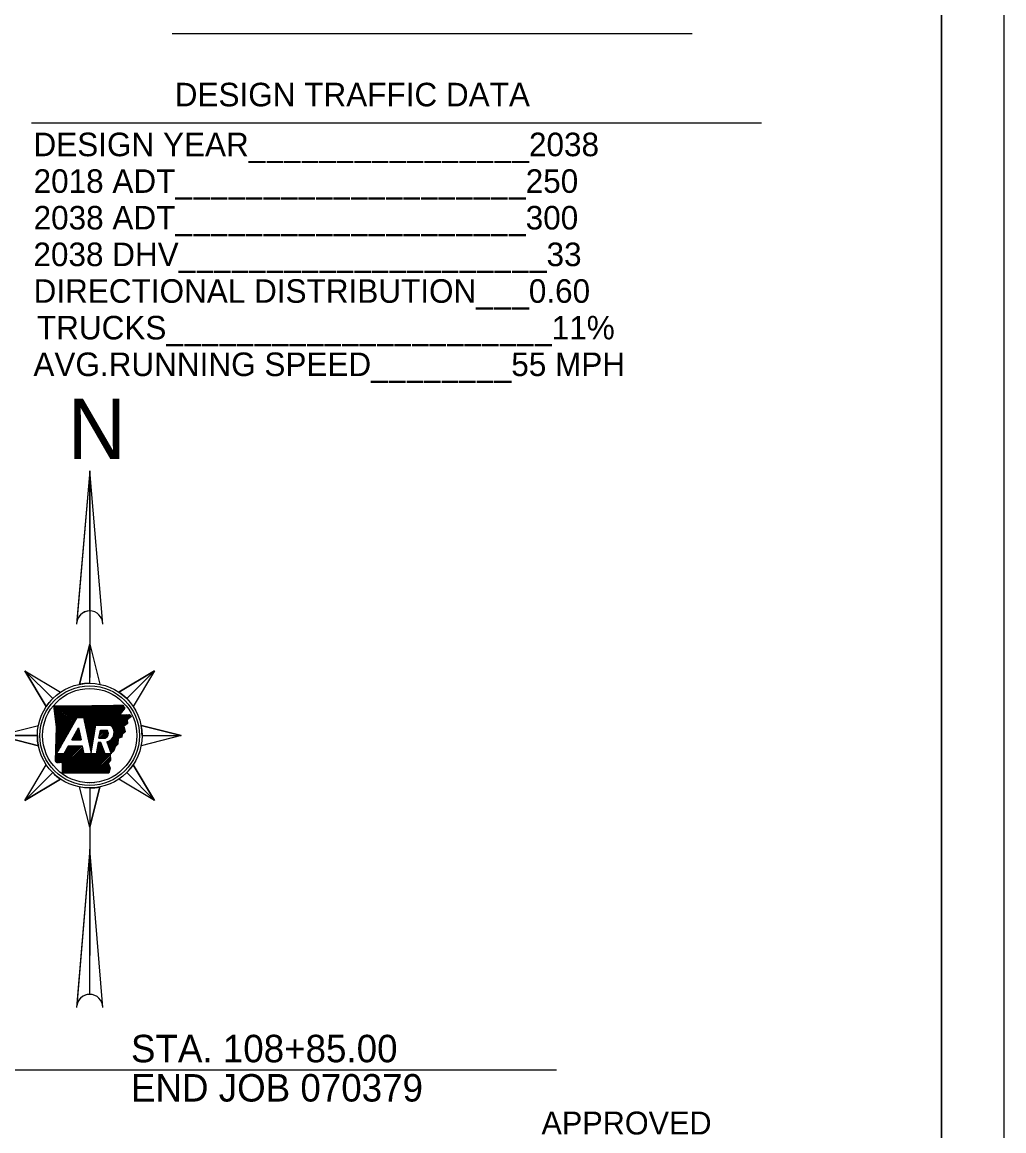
# Model space of a CAD drawing. Extents: x -492261 to -432772, y 1441225 to 1452922.
# Drawn here: x -457499 to -456748, y 1450946 to 1451793 of the extents above; entities that cross this region are included whole.
import ezdxf

# ---------------------------------------------------------------- set-up
doc = ezdxf.new("R2010")
doc.units = 0
for name, color, linetype in [('Default', 7, 'Continuous'), ('R_Border', 7, 'Continuous'), ('R_Border PE', 7, 'Continuous'), ('R_Draft', 7, 'Continuous'), ('R_No Plot', 7, 'Continuous'), ('R_Water Annot', 7, 'Continuous')]:
    doc.layers.add(name, color=color, linetype=linetype)

msp = doc.modelspace()

# ---------------------------------------------------------------- linework, layer by layer
at = {"layer": 'Default'}
for p, q in [((-457383.88, 1451784.26), (-456986.47, 1451784.26)), ((-457491.53, 1451716.09), (-456933.55, 1451716.09))]:
    msp.add_line(p, q, dxfattribs=at)
at = {"layer": 'R_Border'}
msp.add_line((-456795.84, 1450553.05), (-456795.84, 1452607.65), dxfattribs=at)
at = {"layer": 'R_Draft'}
for p, q in [((-457446.98, 1451449.98), (-457456.83, 1451334.68)), ((-457446.98, 1451449.98), (-457446.98, 1451292.07)), ((-457446.98, 1451342.98), (-457446.98, 1451449.98)), ((-457456.69, 1451336.29), (-457456.24, 1451336.73)), ((-457456.64, 1451336.9), (-457455.73, 1451337.82)), ((-457446.98, 1451317.7), (-457454.77, 1451286.93)), ((-457446.98, 1451287.7), (-457446.98, 1451317.7)), ((-457496.47, 1451297.2), (-457475.26, 1451275.98)), ((-457475.26, 1451275.98), (-457496.47, 1451297.2)), ((-457496.47, 1451297.2), (-457480.23, 1451269.93)), ((-457397.48, 1451297.2), (-457424.74, 1451280.95)), ((-457418.69, 1451275.98), (-457397.48, 1451297.2)), ((-457418.69, 1451275.98), (-457397.48, 1451297.2)), ((-457472.24, 1451233.69), (-457456.46, 1451261.56)), ((-457456.46, 1451261.56), (-457451.77, 1451261.56)), ((-457460.63, 1451244.63), (-457455.47, 1451253.74)), ((-457442.25, 1451255.75), (-457431.29, 1451255.75)), ((-457438.83, 1451251.81), (-457433.69, 1451251.81)), ((-457376.98, 1451247.7), (-457407.74, 1451255.49)), ((-457516.98, 1451247.7), (-457486.98, 1451247.7)), ((-457486.98, 1451247.7), (-457516.98, 1451247.7)), ((-457516.98, 1451247.7), (-457486.21, 1451239.91)), ((-457463.51, 1451239.54), (-457466.82, 1451233.69)), ((-457452.43, 1451239.54), (-457463.51, 1451239.54)), ((-457460.63, 1451244.63), (-457453.52, 1451244.63)), ((-457438.55, 1451242.55), (-457440.45, 1451242.55)), ((-457439.87, 1451245.86), (-457435.17, 1451245.86)), ((-457435.27, 1451233.69), (-457438.55, 1451242.55)), ((-457433.91, 1451243.02), (-457430.46, 1451233.69)), ((-457406.98, 1451247.7), (-457376.98, 1451247.7)), ((-457406.98, 1451247.7), (-457376.98, 1451247.7)), ((-457466.82, 1451233.69), (-457472.24, 1451233.69)), ((-457441.99, 1451233.69), (-457451.18, 1451233.69)), ((-457430.46, 1451233.69), (-457435.27, 1451233.69)), ((-457397.48, 1451198.2), (-457413.73, 1451225.46)), ((-457496.47, 1451198.2), (-457475.26, 1451219.42)), ((-457475.26, 1451219.42), (-457496.47, 1451198.2)), ((-457496.47, 1451198.2), (-457469.21, 1451214.45)), ((-457418.69, 1451219.42), (-457397.48, 1451198.2)), ((-457418.69, 1451219.42), (-457397.48, 1451198.2)), ((-457446.98, 1451177.7), (-457439.19, 1451208.47)), ((-457446.98, 1451207.7), (-457446.98, 1451207.7)), ((-457446.98, 1451207.7), (-457446.98, 1451079.65)), ((-457446.98, 1451207.7), (-457446.98, 1451177.7)), ((-457446.98, 1451160.98), (-457456.84, 1451041.62)), ((-457446.98, 1451049.98), (-457446.98, 1451160.98)), ((-457691.3, 1450992.37), (-457090.15, 1450992.37))]:
    msp.add_line(p, q, dxfattribs=at)
for points in [[(-457436.98, 1451332.98), (-457446.98, 1451449.98), (-457456.98, 1451332.98)], [(-457454.77, 1451286.93), (-457446.98, 1451317.7), (-457439.19, 1451286.93)], [(-457480.23, 1451269.93), (-457496.47, 1451297.2), (-457469.21, 1451280.95)], [(-457424.74, 1451280.95), (-457397.48, 1451297.2), (-457413.73, 1451269.93)], [(-457474.29, 1451270.6), (-457458.68, 1451270.59), (-457444.98, 1451270.62), (-457428.82, 1451270.87), (-457421.33, 1451271.04)], [(-457473.16, 1451228.37), (-457472.29, 1451254.55), (-457474.29, 1451270.6)], [(-457451.77, 1451261.56), (-457445.96, 1451234.43), (-457442.25, 1451255.75)], [(-457416.43, 1451263.87), (-457415.08, 1451262.46), (-457418.44, 1451259.69), (-457418.08, 1451256.9), (-457420.97, 1451254.99), (-457419.98, 1451250.7), (-457422.21, 1451248.66), (-457422.41, 1451246.46), (-457425.11, 1451245.48), (-457425.53, 1451241.32), (-457427.48, 1451239.23), (-457428.42, 1451236.1), (-457431.25, 1451233.5), (-457431.04, 1451228.93), (-457432.96, 1451226.77), (-457431.21, 1451222.84), (-457432.42, 1451218.95)], [(-457423.65, 1451263.5), (-457416.32, 1451263.88)], [(-457486.21, 1451239.91), (-457516.98, 1451247.7), (-457486.21, 1451255.49)], [(-457455.47, 1451253.74), (-457453.52, 1451244.63)], [(-457439.87, 1451245.86), (-457438.83, 1451251.81)], [(-457407.74, 1451255.49), (-457376.98, 1451247.7), (-457407.74, 1451239.91)], [(-457451.18, 1451233.69), (-457452.43, 1451239.54)], [(-457440.45, 1451242.55), (-457441.99, 1451233.69)], [(-457469.21, 1451214.45), (-457496.47, 1451198.2), (-457480.23, 1451225.46)], [(-457432.42, 1451218.95), (-457467.8, 1451219), (-457467.82, 1451226.81)], [(-457413.73, 1451225.46), (-457397.48, 1451198.2), (-457424.74, 1451214.45)], [(-457439.19, 1451208.47), (-457446.98, 1451177.7), (-457454.77, 1451208.47)], [(-457436.98, 1451039.98), (-457446.98, 1451160.98), (-457456.98, 1451039.98)]]:
    msp.add_lwpolyline(points, dxfattribs=at)
for radius in [40, 36]:
    msp.add_circle((-457446.98, 1451247.7), radius, dxfattribs=at)
for centre, radius, start, end in [((-457446.98, 1451332.98), 10, 0, 180), ((-457446.98, 1451332.98), 10, 90, 170.22959), ((-457446.98, 1451247.7), 40, 90, 101.22909), ((-457446.98, 1451247.7), 40, 135, 146.22909), ((-457446.98, 1451247.7), 40, 45, 56.22909), ((-457436.29, 1451249.3), 3.62, 288.12683, 43.89016), ((-457435.36, 1451249.95), 7.08, 281.86262, 54.87052), ((-457446.98, 1451247.7), 40, 0, 11.22909), ((-457446.98, 1451247.7), 40, 180, 191.22909), ((-457446.98, 1451247.7), 40, 315, 326.22909), ((-457446.98, 1451247.7), 40, 225, 236.22909), ((-457446.98, 1451247.7), 40, 270, 281.22909), ((-457446.98, 1451039.98), 10, 0, 180), ((-457446.98, 1451039.98), 10, 90, 170.5511)]:
    msp.add_arc(centre, radius, start, end, dxfattribs=at)
for points in [[(-457421.33, 1451271.04), (-457421.28, 1451270.62), (-457421.15, 1451270.39), (-457421.13, 1451269.99), (-457420.96, 1451269.82), (-457420.68, 1451269.64), (-457420.43, 1451269.36), (-457420.38, 1451269.03), (-457420.45, 1451268.7), (-457420.47, 1451268.32), (-457420.51, 1451267.99), (-457420.57, 1451267.69), (-457420.8, 1451267.45), (-457421.02, 1451267.28), (-457421.22, 1451267.07), (-457421.37, 1451266.86), (-457421.62, 1451266.63), (-457421.87, 1451266.39), (-457422.07, 1451266.18), (-457422.28, 1451265.91), (-457422.37, 1451265.61), (-457422.6, 1451265.39), (-457422.77, 1451265.2), (-457423, 1451264.94), (-457423.12, 1451264.68), (-457423.34, 1451264.38), (-457423.39, 1451264.09), (-457423.53, 1451263.86), (-457423.54, 1451263.82)], [(-457467.82, 1451226.81), (-457467.78, 1451226.79), (-457467.96, 1451226.92), (-457468.21, 1451227.04), (-457468.49, 1451227.06), (-457468.85, 1451227.11), (-457469.15, 1451227.14), (-457469.46, 1451227.34), (-457469.79, 1451227.13), (-457470.15, 1451226.98), (-457470.37, 1451227.15), (-457470.65, 1451227.03), (-457470.84, 1451227.09), (-457471.18, 1451226.86), (-457471.5, 1451226.95), (-457471.73, 1451226.88), (-457472.02, 1451226.89), (-457472.08, 1451227.22), (-457472.36, 1451227.27), (-457472.6, 1451227.4), (-457472.76, 1451227.74), (-457472.88, 1451228), (-457473.16, 1451228.37)]]:
    msp.add_spline(points, degree=3, dxfattribs=at)
at = {"layer": 'R_No Plot'}
for points in [[(-460081.71, 1452646.6), (-456748.31, 1452646.6), (-456748.31, 1450513.22), (-460081.71, 1450513.22)], [(-457618.44, 1452607.65), (-457618.44, 1452508.85), (-457261.12, 1452508.85), (-457261.12, 1452479.65), (-457029.12, 1452479.65), (-457029.12, 1452236.32), (-456795.84, 1452236.32), (-456795.84, 1450553.05), (-459957.64, 1450553.05), (-459957.64, 1452607.65)]]:
    msp.add_lwpolyline(points, close=True, dxfattribs=at)
at = {"layer": 'R_Water Annot'}
for p, q in [((-457474.24, 1451270.24), (-457473.89, 1451270.6)), ((-457474.12, 1451269.24), (-457472.76, 1451270.6)), ((-457473.99, 1451268.23), (-457471.63, 1451270.6)), ((-457473.87, 1451267.23), (-457470.5, 1451270.6)), ((-457473.74, 1451266.22), (-457469.37, 1451270.59)), ((-457473.62, 1451265.21), (-457468.24, 1451270.59)), ((-457473.49, 1451264.21), (-457467.11, 1451270.59)), ((-457473.36, 1451263.2), (-457465.97, 1451270.59)), ((-457473.24, 1451262.2), (-457464.84, 1451270.59)), ((-457473.11, 1451261.19), (-457463.71, 1451270.59)), ((-457472.99, 1451260.18), (-457462.58, 1451270.59)), ((-457472.86, 1451259.18), (-457461.45, 1451270.59)), ((-457472.74, 1451258.17), (-457460.32, 1451270.59)), ((-457472.61, 1451257.17), (-457459.19, 1451270.59)), ((-457472.58, 1451245.89), (-457447.85, 1451270.61)), ((-457472.54, 1451247.06), (-457448.99, 1451270.61)), ((-457472.5, 1451248.23), (-457450.12, 1451270.61)), ((-457472.49, 1451256.16), (-457458.06, 1451270.59)), ((-457472.46, 1451249.4), (-457451.26, 1451270.6)), ((-457472.42, 1451250.57), (-457452.39, 1451270.6)), ((-457472.38, 1451251.74), (-457453.52, 1451270.6)), ((-457472.36, 1451255.15), (-457456.92, 1451270.59)), ((-457472.34, 1451252.91), (-457454.66, 1451270.6)), ((-457472.3, 1451254.08), (-457455.79, 1451270.59)), ((-457455.77, 1451261.56), (-457446.72, 1451270.61)), ((-457454.64, 1451261.56), (-457445.59, 1451270.62)), ((-457453.51, 1451261.56), (-457444.45, 1451270.63)), ((-457452.38, 1451261.56), (-457443.3, 1451270.64)), ((-457451.68, 1451261.13), (-457442.15, 1451270.66)), ((-457451.48, 1451260.2), (-457441, 1451270.68)), ((-457451.28, 1451259.27), (-457439.85, 1451270.7)), ((-457451.08, 1451258.34), (-457438.7, 1451270.71)), ((-457450.88, 1451257.4), (-457437.55, 1451270.73)), ((-457450.68, 1451256.47), (-457436.4, 1451270.75)), ((-457450.48, 1451255.54), (-457435.25, 1451270.77)), ((-457450.28, 1451254.61), (-457434.1, 1451270.79)), ((-457450.08, 1451253.68), (-457432.95, 1451270.8)), ((-457449.88, 1451252.75), (-457431.8, 1451270.82)), ((-457449.68, 1451251.81), (-457430.66, 1451270.84)), ((-457449.48, 1451250.88), (-457429.51, 1451270.86)), ((-457449.28, 1451249.95), (-457428.35, 1451270.88)), ((-457449.08, 1451249.02), (-457427.19, 1451270.91)), ((-457441.22, 1451255.75), (-457426.04, 1451270.93)), ((-457440.09, 1451255.75), (-457424.88, 1451270.96)), ((-457438.96, 1451255.75), (-457423.72, 1451270.99)), ((-457437.83, 1451255.75), (-457422.56, 1451271.01)), ((-457436.7, 1451255.75), (-457421.4, 1451271.04)), ((-457435.57, 1451255.75), (-457421.15, 1451270.16)), ((-457434.44, 1451255.75), (-457420.6, 1451269.58)), ((-457433.3, 1451255.75), (-457420.46, 1451268.59)), ((-457432.17, 1451255.75), (-457423.04, 1451264.88)), ((-457472.65, 1451243.55), (-457458.82, 1451257.38)), ((-457472.61, 1451244.72), (-457457.35, 1451259.99)), ((-457431.14, 1451255.64), (-457423.26, 1451263.52)), ((-457430.53, 1451255.13), (-457422.07, 1451263.58)), ((-457429.97, 1451254.55), (-457420.88, 1451263.65)), ((-457429.49, 1451253.91), (-457419.69, 1451263.71)), ((-457429.07, 1451253.19), (-457418.49, 1451263.77)), ((-457428.72, 1451252.41), (-457417.3, 1451263.83)), ((-457428.54, 1451248.07), (-457418.27, 1451258.34)), ((-457428.46, 1451251.54), (-457416.23, 1451263.77)), ((-457428.31, 1451250.56), (-457415.7, 1451263.17)), ((-457428.3, 1451249.44), (-457418.4, 1451259.34)), ((-457419.54, 1451255.94), (-457418.14, 1451257.34)), ((-457416.2, 1451261.54), (-457415.17, 1451262.57)), ((-457472.77, 1451240.04), (-457463.26, 1451249.55)), ((-457472.73, 1451241.21), (-457461.78, 1451252.16)), ((-457472.69, 1451242.38), (-457460.3, 1451254.77)), ((-457460.57, 1451244.63), (-457454.76, 1451250.44)), ((-457459.44, 1451244.63), (-457454.56, 1451249.51)), ((-457459.22, 1451247.11), (-457454.96, 1451251.37)), ((-457458.31, 1451244.63), (-457454.36, 1451248.58)), ((-457457.75, 1451249.72), (-457455.16, 1451252.31)), ((-457456.27, 1451252.33), (-457455.36, 1451253.24)), ((-457448.88, 1451248.09), (-457442.46, 1451254.51)), ((-457448.68, 1451247.15), (-457442.7, 1451253.14)), ((-457448.48, 1451246.22), (-457442.94, 1451251.77)), ((-457448.29, 1451245.29), (-457443.18, 1451250.39)), ((-457448.09, 1451244.36), (-457443.42, 1451249.02)), ((-457439.86, 1451245.86), (-457433.91, 1451251.81)), ((-457439.63, 1451247.22), (-457435.04, 1451251.81)), ((-457439.39, 1451248.59), (-457436.17, 1451251.81)), ((-457439.15, 1451249.96), (-457437.3, 1451251.81)), ((-457438.91, 1451251.33), (-457438.44, 1451251.81)), ((-457438.73, 1451245.86), (-457433.28, 1451251.31)), ((-457437.6, 1451245.86), (-457432.9, 1451250.56)), ((-457436.47, 1451245.86), (-457432.69, 1451249.64)), ((-457435.34, 1451245.86), (-457432.78, 1451248.41)), ((-457433.21, 1451241.13), (-457420.67, 1451253.68)), ((-457432.9, 1451240.31), (-457420.45, 1451252.76)), ((-457432.6, 1451239.48), (-457420.24, 1451251.84)), ((-457432.29, 1451238.66), (-457420.03, 1451250.92)), ((-457429.52, 1451245.95), (-457420.88, 1451254.6)), ((-457472.89, 1451236.53), (-457467.69, 1451241.73)), ((-457472.85, 1451237.7), (-457466.21, 1451244.34)), ((-457472.81, 1451238.87), (-457464.73, 1451246.94)), ((-457472.72, 1451227.64), (-457460.83, 1451239.54)), ((-457472.05, 1451227.19), (-457459.7, 1451239.54)), ((-457471.23, 1451226.87), (-457458.56, 1451239.54)), ((-457469.89, 1451227.08), (-457457.43, 1451239.54)), ((-457468.74, 1451227.1), (-457456.3, 1451239.54)), ((-457467.85, 1451226.85), (-457455.17, 1451239.54)), ((-457467.82, 1451225.76), (-457454.04, 1451239.54)), ((-457467.81, 1451224.63), (-457452.91, 1451239.54)), ((-457465.54, 1451235.95), (-457461.96, 1451239.54)), ((-457464.06, 1451238.56), (-457463.09, 1451239.54)), ((-457457.18, 1451244.63), (-457454.16, 1451247.65)), ((-457456.05, 1451244.63), (-457453.96, 1451246.71)), ((-457454.92, 1451244.63), (-457453.76, 1451245.78)), ((-457453.79, 1451244.63), (-457453.56, 1451244.85)), ((-457447.89, 1451243.43), (-457443.66, 1451247.65)), ((-457447.69, 1451242.49), (-457443.9, 1451246.28)), ((-457447.49, 1451241.56), (-457444.14, 1451244.91)), ((-457447.29, 1451240.63), (-457444.37, 1451243.54)), ((-457447.09, 1451239.7), (-457444.61, 1451242.17)), ((-457446.89, 1451238.77), (-457444.85, 1451240.8)), ((-457446.69, 1451237.83), (-457445.09, 1451239.43)), ((-457441.56, 1451236.18), (-457437.64, 1451240.1)), ((-457441.32, 1451237.55), (-457437.94, 1451240.92)), ((-457441.08, 1451238.92), (-457438.25, 1451241.75)), ((-457440.84, 1451240.29), (-457438.58, 1451242.55)), ((-457440.6, 1451241.66), (-457439.71, 1451242.55)), ((-457433.82, 1451242.79), (-457433.47, 1451243.13)), ((-457433.51, 1451241.96), (-457431.36, 1451244.11)), ((-457431.99, 1451237.83), (-457425.2, 1451244.62)), ((-457431.68, 1451237), (-457425.33, 1451243.36)), ((-457431.38, 1451236.18), (-457425.45, 1451242.1)), ((-457423.9, 1451245.92), (-457422.31, 1451247.51)), ((-457473.14, 1451228.35), (-457467.81, 1451233.69)), ((-457473.12, 1451229.51), (-457468.94, 1451233.69)), ((-457473.08, 1451230.68), (-457470.07, 1451233.69)), ((-457473.04, 1451231.85), (-457471.2, 1451233.69)), ((-457473, 1451233.02), (-457472.12, 1451233.9)), ((-457472.96, 1451234.19), (-457470.64, 1451236.51)), ((-457472.92, 1451235.36), (-457469.16, 1451239.12)), ((-457467.81, 1451223.5), (-457452.31, 1451239)), ((-457467.81, 1451222.37), (-457452.11, 1451238.07)), ((-457467.8, 1451221.24), (-457451.91, 1451237.14)), ((-457467.8, 1451220.12), (-457451.71, 1451236.2)), ((-457467.78, 1451219), (-457451.51, 1451235.27)), ((-457466.65, 1451219), (-457451.31, 1451234.34)), ((-457465.52, 1451219), (-457450.84, 1451233.69)), ((-457464.39, 1451219), (-457449.71, 1451233.69)), ((-457463.26, 1451219), (-457448.57, 1451233.69)), ((-457462.14, 1451218.99), (-457447.44, 1451233.69)), ((-457461.01, 1451218.99), (-457446.31, 1451233.69)), ((-457459.88, 1451218.99), (-457445.18, 1451233.69)), ((-457458.75, 1451218.99), (-457444.05, 1451233.69)), ((-457457.62, 1451218.99), (-457442.92, 1451233.69)), ((-457456.49, 1451218.99), (-457437.03, 1451238.44)), ((-457455.36, 1451218.98), (-457436.72, 1451237.62)), ((-457454.23, 1451218.98), (-457436.42, 1451236.79)), ((-457453.1, 1451218.98), (-457436.11, 1451235.97)), ((-457451.97, 1451218.98), (-457435.81, 1451235.14)), ((-457450.84, 1451218.98), (-457435.5, 1451234.31)), ((-457449.71, 1451218.97), (-457435, 1451233.69)), ((-457448.58, 1451218.97), (-457433.87, 1451233.69)), ((-457447.45, 1451218.97), (-457432.73, 1451233.69)), ((-457446.49, 1451236.9), (-457445.33, 1451238.06)), ((-457446.32, 1451218.97), (-457431.6, 1451233.69)), ((-457446.29, 1451235.97), (-457445.57, 1451236.69)), ((-457446.09, 1451235.04), (-457445.81, 1451235.32)), ((-457445.19, 1451218.97), (-457431.22, 1451232.93)), ((-457444.06, 1451218.96), (-457431.17, 1451231.85)), ((-457441.79, 1451234.81), (-457437.33, 1451239.27)), ((-457431.07, 1451235.35), (-457427.6, 1451238.82)), ((-457430.77, 1451234.52), (-457428.09, 1451237.2)), ((-457442.93, 1451218.96), (-457431.12, 1451230.77)), ((-457441.8, 1451218.96), (-457431.07, 1451229.69)), ((-457440.67, 1451218.96), (-457432.93, 1451226.7)), ((-457439.54, 1451218.96), (-457432.58, 1451225.92)), ((-457438.42, 1451218.96), (-457432.23, 1451225.14)), ((-457437.29, 1451218.95), (-457431.88, 1451224.36)), ((-457436.16, 1451218.95), (-457431.53, 1451223.57)), ((-457435.03, 1451218.95), (-457431.24, 1451222.74)), ((-457433.9, 1451218.95), (-457431.75, 1451221.09)), ((-457432.77, 1451218.95), (-457432.27, 1451219.45))]:
    msp.add_line(p, q, dxfattribs=at)
msp.add_circle((-457446.98, 1451247.7), 38, dxfattribs=at)

# ---------------------------------------------------------------- texts
at = {"layer": 'Default'}
for s, p in [('DESIGN TRAFFIC DATA', (-457381.98, 1451728.59)), ('DESIGN YEAR________________2038', (-457489.94, 1451690.48)), ('2018 ADT____________________250', (-457489.86, 1451662.48)), ('2038 ADT____________________300', (-457489.86, 1451634.48)), ('2038 DHV_____________________33', (-457489.99, 1451606.48)), ('DIRECTIONAL DISTRIBUTION___0.60', (-457489.86, 1451578.48)), ('TRUCKS______________________11%', (-457487.33, 1451550.48)), ('AVG.RUNNING SPEED________55 MPH', (-457489.99, 1451522.48))]:
    msp.add_text(s, height=18, dxfattribs=at).set_placement(p)
at = {"layer": 'R_Border PE'}
msp.add_text('APPROVED', height=17.496, dxfattribs=at).set_placement((-457101.7, 1450942.93))
at = {"layer": 'R_Draft'}
for s, height, p in [('N', 46.15, (-457463.84, 1451459.06)), ('DWB 7-27-17', 0.7778, (-457449.43, 1451211.03)), ('STA. 108+85.00', 21, (-457415.44, 1450998.1)), ('END JOB 070379', 21, (-457415.44, 1450968.1))]:
    msp.add_text(s, height=height, dxfattribs=at).set_placement(p)

doc.saveas('drawing.dxf')
